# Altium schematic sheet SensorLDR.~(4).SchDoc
size A
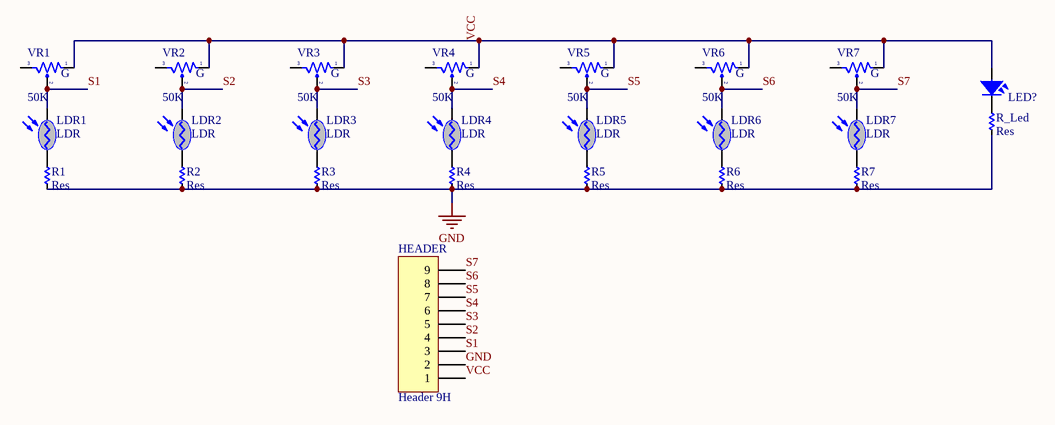
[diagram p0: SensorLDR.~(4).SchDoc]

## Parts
HEADER  Header 9H  [HDR1X9H]
LDR1  LDR  [CDS]
LDR2  LDR  [CDS]
LDR3  LDR  [CDS]
LDR4  LDR  [CDS]
LDR5  LDR  [CDS]
LDR6  LDR  [CDS]
LDR7  LDR  [CDS]
LED?  LED  [LED-3MM-YELLOW]  (value not drawn)
R1  Res  [RES-1/2W]
R2  Res  [RES-1/2W]
R3  Res  [RES-1/2W]
R4  Res  [RES-1/2W]
R5  Res  [RES-1/2W]
R6  Res  [RES-1/2W]
R7  Res  [RES-1/2W]
R_Led  Res  [RES-1/2W]
VR1  50K  [VR-S1]
VR2  50K  [VR-S1]
VR3  50K  [VR-S1]
VR4  50K  [VR-S1]
VR5  50K  [VR-S1]
VR6  50K  [VR-S1]
VR7  50K  [VR-S1]

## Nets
GND: HEADER.2 R1.2 R2.2 R3.2 R4.2 R5.2 R6.2 R7.2 R_Led.2
S1: HEADER.3 LDR1.2(K) VR1.2
S2: HEADER.4 LDR2.2(K) VR2.2
S3: HEADER.5 LDR3.2(K) VR3.2
S4: HEADER.6 LDR4.2(K) VR4.2
S5: HEADER.7 LDR5.2(K) VR5.2
S6: HEADER.8 LDR6.2(K) VR6.2
S7: HEADER.9 LDR7.2(K) VR7.2
VCC: HEADER.1 LED?.1 VR1.1 VR2.1 VR3.1 VR4.1 VR5.1 VR6.1 VR7.1
NetLDR1_1: LDR1.1(A) R1.1
NetLDR2_1: LDR2.1(A) R2.1
NetLDR3_1: LDR3.1(A) R3.1
NetLDR4_1: LDR4.1(A) R4.1
NetLDR5_1: LDR5.1(A) R5.1
NetLDR6_1: LDR6.1(A) R6.1
NetLDR7_1: LDR7.1(A) R7.1
NetLED?_2: LED?.2 R_Led.1

Not connected (* = marked no-connect by the designer): VR1 3; VR2 3; VR3 3; VR4 3; VR5 3; VR6 3; VR7 3

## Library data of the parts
HEADER = Header 9H: Header, 9-Pin, Right Angle
LDR1-LDR7 = LDR: Quang Tro
LED? = LED: LED Single colour Green and Red; Value: LED 3 ly Single Colour
R1-R7 R_Led = Res: Manufacturer: Generic Components; Class: Passive; SubClass: R
VR1-VR7 = VR-S: Var Resistor; Value: Volume 50k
